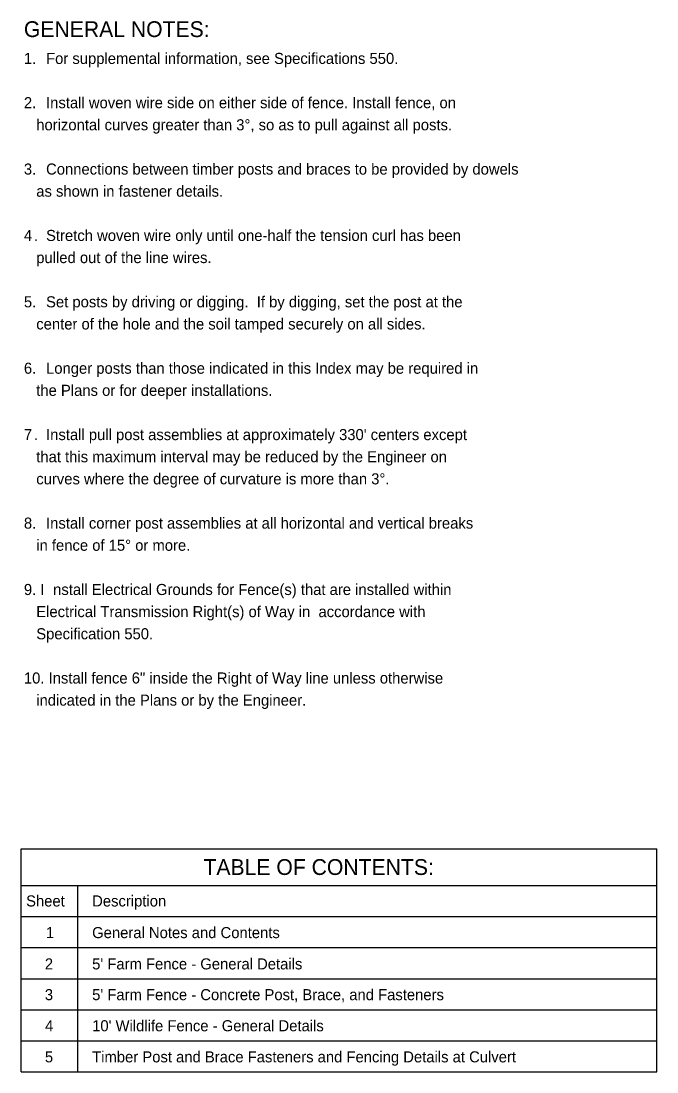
# Model space of a CAD drawing. Extents: x -32.8 to 6.1, y 1.7 to 8.3.
# Drawn here: x 2.12 to 6.14, y 1.69 to 8.34 of the extents above; entities that cross this region are included whole.
import ezdxf

# ---------------------------------------------------------------- set-up
doc = ezdxf.new("R2010")
doc.units = 0
for name, color, linetype in [('Default', 7, 'Continuous'), ('Table', 7, 'Continuous'), ('TextStructures', 7, 'Continuous')]:
    doc.layers.add(name, color=color, linetype=linetype)

msp = doc.modelspace()

# ---------------------------------------------------------------- linework, layer by layer
at = {"layer": 'Table'}
for p, q in [((2.1239, 1.6884), (2.1239, 3.1008)), ((2.1239, 3.1008), (6.1441, 3.1008)), ((6.1441, 1.6884), (6.1441, 3.1008)), ((2.1239, 2.8689), (6.1441, 2.8689)), ((2.4838, 1.6884), (2.4838, 2.8689)), ((2.1239, 2.6722), (6.1441, 2.6722)), ((2.1239, 2.4754), (6.1441, 2.4754)), ((2.1239, 2.2787), (6.1441, 2.2787)), ((2.1239, 2.0819), (6.1441, 2.0819)), ((2.1239, 1.8852), (6.1441, 1.8852)), ((2.1239, 1.6884), (6.1441, 1.6884))]:
    msp.add_line(p, q, dxfattribs=at)

# ---------------------------------------------------------------- texts
at = {"layer": 'Default'}
for s, p in [('1.', (2.1421, 8.066)), ('For supplemental information, see Specifications 550.', (2.2821, 8.066)), ('2.', (2.1421, 7.786)), ('Install woven wire side on either side of fence. Install fence, on ', (2.2821, 7.786)), ('   horizontal curves greater than 3°, so as to pull against all posts.', (2.1421, 7.646)), ('3.', (2.1421, 7.366)), ('Connections between timber posts and braces to be provided by dowels ', (2.2821, 7.366)), ('   as shown in fastener details.', (2.1421, 7.226)), ('4', (2.1421, 6.946)), ('Stretch woven wire only until one-half the tension curl has been ', (2.2821, 6.946)), ('.', (2.2049, 6.946)), ('   pulled out of the line wires.', (2.1421, 6.806)), ('5.', (2.1421, 6.526)), ('Set posts by driving or digging.  If by digging, set the post at the ', (2.2821, 6.526)), ('   center of the hole and the soil tamped securely on all sides.', (2.1421, 6.386)), ('6.', (2.1421, 6.106)), ('Longer posts than those indicated in this Index may be required in', (2.2821, 6.106)), ('   the Plans or for deeper installations.', (2.1421, 5.966)), ('7', (2.1421, 5.686)), ("Install pull post assemblies at approximately 330' centers except ", (2.2821, 5.686)), ('.', (2.2049, 5.686)), ('   that this maximum interval may be reduced by the Engineer on ', (2.1421, 5.546)), ('   curves where the degree of curvature is more than 3°.', (2.1421, 5.406)), ('8.', (2.1421, 5.126)), ('Install corner post assemblies at all horizontal and vertical breaks ', (2.2821, 5.126)), ('   in fence of 15° or more.', (2.1421, 4.986)), ('9. I', (2.1421, 4.706)), ('nstall Electrical Grounds for Fence(s) that are installed within ', (2.3268, 4.706)), ('   Electrical Transmission Right(s) of Way in  accordance with ', (2.1421, 4.566)), ('   Specification 550.', (2.1421, 4.426)), ('10. Install fence 6" inside the Right of Way line unless otherwise ', (2.1421, 4.146)), ('   indicated in the Plans or by the Engineer.', (2.1421, 4.006))]:
    msp.add_text(s, height=0.07, dxfattribs=at).set_placement(p)
at = {"layer": 'Table'}
for s, height, p in [('TABLE OF CONTENTS:', 0.1, (3.2773, 2.9349)), ('Sheet', 0.07, (2.1559, 2.7355)), ('Description', 0.07, (2.5735, 2.7355)), ('1', 0.07, (2.2808, 2.5353)), ('General Notes and Contents', 0.07, (2.5735, 2.5353)), ('2', 0.07, (2.2745, 2.3373)), ("5' Farm Fence - General Details", 0.07, (2.5735, 2.3373)), ('3', 0.07, (2.2745, 2.1427)), ("5' Farm Fence - Concrete Post, Brace, and Fasteners", 0.07, (2.5735, 2.1427)), ('4', 0.07, (2.2759, 1.946)), ("10' Wildlife Fence - General Details", 0.07, (2.5735, 1.946)), ('5', 0.07, (2.2748, 1.7492)), ('Timber Post and Brace Fasteners and Fencing Details at Culvert', 0.07, (2.5735, 1.7492))]:
    msp.add_text(s, height=height, dxfattribs=at).set_placement(p)
at = {"layer": 'TextStructures'}
msp.add_text('GENERAL NOTES:', height=0.1, dxfattribs=at).set_placement((2.1421, 8.236))

doc.saveas('drawing.dxf')
